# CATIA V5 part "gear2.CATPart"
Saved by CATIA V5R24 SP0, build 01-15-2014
Part number: gear2
Bounding box of the stored display mesh (mm): x -32 to 32, y -31.825 to 31.825, z -10 to 10
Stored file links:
  G:\내 드라이브\04_WORK\00_LECTURE\CAD2020\exam\gear2.CATPart
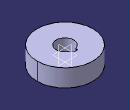
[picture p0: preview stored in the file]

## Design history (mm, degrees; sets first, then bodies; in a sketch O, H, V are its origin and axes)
Body1 (main body)
  Sketch1 on xy-plane, origin (0, 0, 0), H (1, 0, 0), V (0, 1, 0)
    arc A1 centre (0, 0) radius 10 from (-2.5, 9.6825) to (2.5, 9.6825) ccw
    circle A2 centre (0, 0) radius 32
    point P1 (0, 3.7776)
    line L1 (2.5, 12) -> (2.5, 9.6825)
    line L2 (-2.5, 9.6825) -> (-2.5, 12)
    line L3 (-2.5, 12) -> (2.5, 12)
    radius A1 = 10
    radius A2 = 32
    distance L1 L2 = 5
    distance L3 H = 12
    coincidence: P1 V
    vertical: L1 V, L2 V
    horizontal: L3 H
    equidistance: L1 L2 P1
  Pad1: profile Sketch1, direction (0, 0, 1), length 10, mirrored extent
